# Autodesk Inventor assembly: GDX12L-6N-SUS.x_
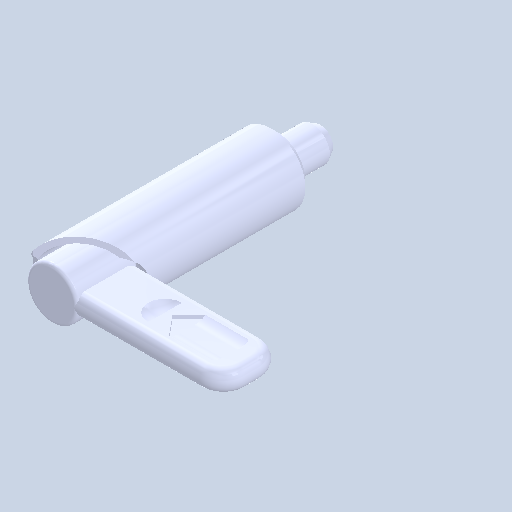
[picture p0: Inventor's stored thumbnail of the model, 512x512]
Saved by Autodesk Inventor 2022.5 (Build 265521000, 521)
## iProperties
Created: 2024-06
Part Number: GDX12L-6N-SUS.x_
Document SubType Name: Assembly
Designer: ImaoCorp
Author: ImaoCorp
Sending System: SOLIDWORKS 2022-2022290
MC: AMD64
MC_MODEL: Intel64 Family 6 Model 60 Stepping 3, GenuineIntel
OS: Windows_NT
FRU: Parasolid Version 33.1, build 260,  4-25-2022
FORMAT: text
GUISE: transmit
KEY: FILEGDX12L-6N-SUS.x_t
DATE: Wed Jun 12 09:31:47 2024
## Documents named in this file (3)
- Y:\5.更新分\2024年対応\xxxx_GDX\データ_imao品番\gdx12l-6n-sus\GDX12L-6N-SUS.x_.iam
- Y:\5.更新分\2024年対応\xxxx_GDX\データ_imao品番\gdx12l-6n-sus\GDX12L-6N-SUS_01.ipt
- Y:\5.更新分\2024年対応\xxxx_GDX\データ_imao品番\gdx12l-6n-sus\GDX12L-6N-SUS_02.ipt
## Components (2 placed, 2 different names)
1. GDX12L-6N-SUS_01
2. GDX12L-6N-SUS_02
